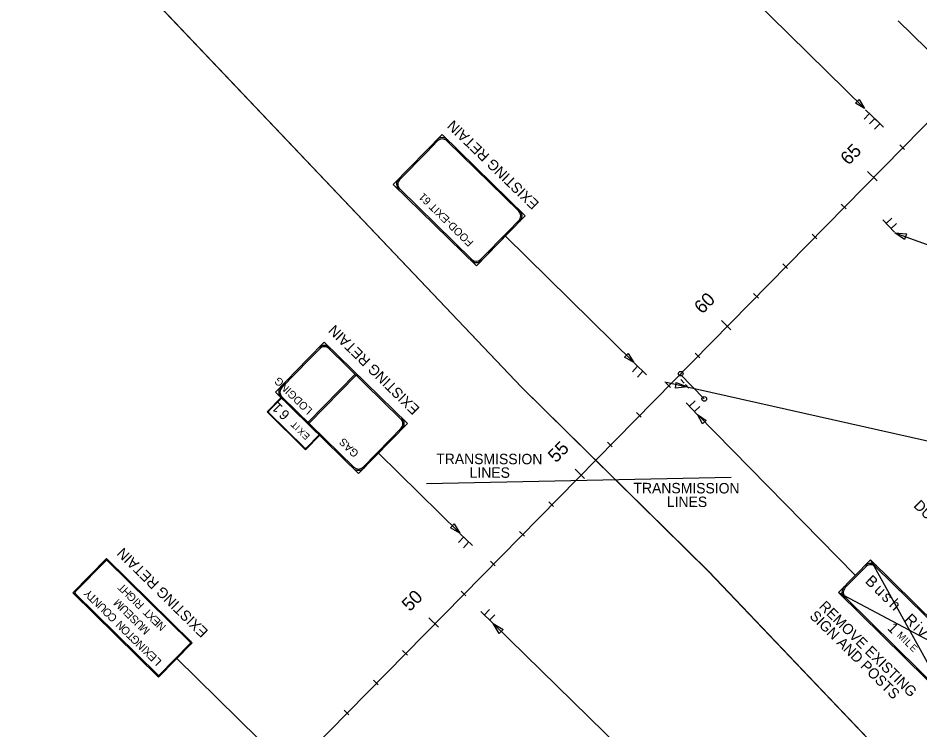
# Model space of a CAD drawing. Extents: x -5665 to 1997148, y 4 to 812485.
# Drawn here: x 1957173 to 1959336, y 794430 to 796136 of the extents above; entities that cross this region are included whole.
import ezdxf

# ---------------------------------------------------------------- set-up
doc = ezdxf.new("R2010")
doc.units = 0
for name, color, linetype in [('RD_HC_CL_Rel', 7, 'Continuous'), ('RD_HC_Data_Tic_Rel', 7, 'Continuous'), ('RD_HC_TX_Rel_Sta50', 7, 'Continuous'), ('RD_PD_Final_TX', 7, 'Continuous'), ('RD_SHT_ShtClip', 7, 'Continuous'), ('RD_SHT_TX', 7, 'Continuous'), ('TR SN EXTRUDED PANEL SIGNS- MOUNTED OVERHEAD', 7, 'Continuous')]:
    doc.layers.add(name, color=color, linetype=linetype)

msp = doc.modelspace()

# ---------------------------------------------------------------- linework, layer by layer
at = {"layer": 'RD_HC_CL_Rel'}
msp.add_line((1957622, 794124.4), (1963740.1, 800343.8), dxfattribs=at)
at = {"layer": 'RD_HC_Data_Tic_Rel'}
for p, q in [((1959299.2, 795820.8), (1959287.8, 795832)), ((1959233.3, 795745.3), (1959210.5, 795767.7)), ((1959158.9, 795678.2), (1959147.5, 795689.4)), ((1959088.8, 795606.9), (1959077.4, 795618.2)), ((1959018.7, 795535.6), (1959007.3, 795546.9)), ((1958948.6, 795464.4), (1958937.2, 795475.6)), ((1958882.7, 795388.9), (1958859.9, 795411.3)), ((1958808.3, 795321.8), (1958796.9, 795333)), ((1958738.2, 795250.5), (1958726.8, 795261.7)), ((1958668, 795179.2), (1958656.6, 795190.4)), ((1958597.9, 795107.9), (1958586.5, 795119.1)), ((1958532.1, 795032.4), (1958509.3, 795054.9)), ((1958457.7, 794965.3), (1958446.3, 794976.6)), ((1958387.5, 794894), (1958376.1, 794905.3)), ((1958317.4, 794822.8), (1958306, 794834)), ((1958247.3, 794751.5), (1958235.9, 794762.7)), ((1958181.4, 794676), (1958158.6, 794698.4)), ((1958107, 794608.9), (1958095.6, 794620.1)), ((1958036.9, 794537.6), (1958025.5, 794548.8)), ((1957966.8, 794466.3), (1957955.4, 794477.5))]:
    msp.add_line(p, q, dxfattribs=at)
at = {"layer": 'RD_PD_Final_TX'}
for points in [[(1959303.9, 795618.3), (1959299.1, 795605.4), (1959275.7, 795621.4)], [(1958750.3, 795248.4), (1958751.9, 795262.1), (1958778.5, 795252)], [(1958336.9, 794670.6), (1958327.3, 794660.8), (1958312.4, 794685)]]:
    msp.add_lwpolyline(points, close=True, dxfattribs=at)
at = {"layer": 'RD_SHT_ShtClip'}
for points in [[(1962404, 800141.4), (1963753.3, 798814), (1964835.2, 797771.3), (1960364.2, 793199.8), (1958829.3, 794809.7), (1958381.6, 795250.1), (1957464.7, 796215.1), (1961650.1, 800469.8)], [(1958379.6, 795252.1), (1958829.6, 794809.5), (1959976.9, 793606), (1955596.7, 789155.3), (1952602.5, 792100.6), (1957064.4, 796636.4)]]:
    msp.add_lwpolyline(points, close=True, dxfattribs=at)
at = {"layer": 'RD_SHT_TX'}
for p, q in [((1959283.6, 796129.4), (1959744.5, 795676)), ((1958152.5, 795020.6), (1958883.8, 795035.8))]:
    msp.add_line(p, q, dxfattribs=at)
at = {"layer": 'TR SN EXTRUDED PANEL SIGNS- MOUNTED OVERHEAD'}
for p, q in [((1959203.3, 795918.8), (1958932.4, 796185.4)), ((1959235.3, 795887.5), (1959205.8, 795916)), ((1959202.3, 795893), (1959214.7, 795905.8)), ((1959215.2, 795881.9), (1959227.6, 795894.7)), ((1959248.6, 795874.5), (1959219, 795903)), ((1959227.4, 795869.2), (1959239.8, 795882)), ((1959268.4, 795656.5), (1959255.5, 795644.2)), ((1959247, 795652.1), (1959275.3, 795622.4)), ((1959280, 795643.3), (1959267.1, 795631)), ((1958649.8, 795310.3), (1958342.1, 795613.2)), ((1959275.7, 795621.4), (1959798.6, 795428.3)), ((1958646.6, 795288.2), (1958659, 795301.1)), ((1958680, 795280.8), (1958650.5, 795309.3)), ((1958658.8, 795275.5), (1958671.2, 795288.4)), ((1958761.3, 795282), (1958818.9, 795223.1)), ((1958762.5, 795269.3), (1958770.8, 795260.8)), ((1958724.1, 795264.2), (1959465.4, 795097.8)), ((1958773.8, 795257.4), (1958782.1, 795248.9)), ((1958775.5, 795213.9), (1958803.8, 795184.2)), ((1958796.9, 795218.3), (1958783.9, 795206)), ((1958808.5, 795205.1), (1958795.6, 795192.8)), ((1959180.6, 794800.3), (1958802.5, 795185.6)), ((1958232.4, 794901.5), (1958037.8, 795093)), ((1958262.8, 794872.1), (1958232.9, 794900.2)), ((1958229.3, 794879.1), (1958241.6, 794892)), ((1958241.7, 794866.5), (1958253.9, 794879.5)), ((1959217.9, 794837.3), (1959404.5, 794499.4)), ((1959140.7, 794758.9), (1959481.6, 794577.8)), ((1958283.2, 794713.3), (1958312.7, 794684.8)), ((1958304.3, 794718.6), (1958291.9, 794705.8)), ((1958316.5, 794705.9), (1958304.1, 794693.1)), ((1958312.4, 794685), (1958618.7, 794385.5)), ((1957750.5, 794407.9), (1957553.7, 794601.5))]:
    msp.add_line(p, q, dxfattribs=at)
for points in [[(1959181.3, 795931.8), (1959190, 795940.6), (1959203.3, 795918.8)], [(1958627.8, 795323.3), (1958636.4, 795332.2), (1958649.8, 795310.3)], [(1958823.8, 795171.5), (1958814.6, 795163.1), (1958802.5, 795185.6)], [(1958210.4, 794914.4), (1958219.1, 794923.3), (1958232.4, 794901.5)]]:
    msp.add_lwpolyline(points, close=True, dxfattribs=at)
for points in [[(1958389.6, 795661.8), (1958190.3, 795856.8), (1958151.3, 795816.9)], [(1958179.5, 795841.3), (1958153.5, 795814.7)], [(1958374.2, 795672.6), (1958201.4, 795841.6)], [(1958151.3, 795816.9), (1958073.3, 795737.2), (1958272.7, 795542.2), (1958350.6, 795622), (1958350.6, 795622)], [(1958153.5, 795814.7), (1958088.5, 795748.3)], [(1958088.8, 795726.4), (1958261.5, 795557.4)], [(1958350.6, 795622), (1958389.6, 795661.8), (1958389.6, 795661.8)], [(1958348.4, 795624.1), (1958374.4, 795650.7)], [(1958283.4, 795557.7), (1958348.4, 795624.1)], [(1958350.6, 795622), (1958285.7, 795555.5)], [(1958107.1, 795163.8), (1957907.7, 795358.8), (1957868.7, 795318.9)], [(1957896.9, 795343.3), (1957871, 795316.7)], [(1958091.6, 795174.6), (1957918.9, 795343.6)], [(1957868.7, 795318.9), (1957790.8, 795239.2), (1957990.1, 795044.2), (1958068.1, 795124), (1958068.1, 795124)], [(1957871, 795316.7), (1957806, 795250.3)], [(1957981.5, 795282.3), (1957869.2, 795167.4)], [(1957984, 795279.8), (1957871.7, 795165)], [(1957804.1, 795226.2), (1957770.5, 795191.9), (1957863, 795101.4), (1957896.6, 795135.7), (1957896.6, 795135.7)], [(1957805.2, 795225.1), (1957775, 795194.2)], [(1957806.2, 795228.4), (1957979, 795059.4)], [(1957775.1, 795189.7), (1957860.7, 795105.9)], [(1958068.1, 795124), (1958107.1, 795163.8), (1958107.1, 795163.8)], [(1958065.9, 795126.1), (1958091.8, 795152.7)], [(1957865.3, 795105.9), (1957895.4, 795136.8)], [(1958000.9, 795059.7), (1958065.9, 795126.1)], [(1957591.2, 794638.7), (1957385.9, 794840.6), (1957305.1, 794758.5), (1957510.4, 794556.5), (1957591.2, 794638.7), (1957591.2, 794638.7), (1957591.2, 794638.7)], [(1957383.8, 794835.1), (1957310.6, 794760.7)], [(1957383.8, 794835.1), (1957383.8, 794835.1), (1957383.8, 794835.1)], [(1957585.7, 794640.7), (1957388.1, 794835.1)], [(1959140.7, 794758.9), (1959404.5, 794499.4), (1959481.6, 794577.8), (1959217.9, 794837.3), (1959140.7, 794758.9), (1959140.7, 794758.9), (1959140.7, 794758.9)], [(1959206.2, 794820.7), (1959157.1, 794770.8)], [(1959206.2, 794820.7), (1959206.2, 794820.7), (1959206.2, 794820.7)], [(1959465, 794589.4), (1959229.8, 794820.9)], [(1957310.7, 794756.4), (1957508.3, 794562)], [(1957310.7, 794756.4), (1957310.7, 794756.4), (1957310.7, 794756.4)], [(1959157.3, 794747.2), (1959392.6, 794515.8)], [(1959157.3, 794747.2), (1959157.3, 794747.2), (1959157.3, 794747.2)], [(1957585.7, 794640.7), (1957585.7, 794640.7), (1957585.7, 794640.7)], [(1957512.5, 794562.1), (1957585.7, 794636.5)], [(1957512.5, 794562.1), (1957512.5, 794562.1), (1957512.5, 794562.1)]]:
    msp.add_lwpolyline(points, dxfattribs=at)
for centre in [(1958762.6, 795283.5), (1958818.9, 795223.1)]:
    msp.add_circle(centre, 5.54, dxfattribs=at)
for centre, radius, start, end in [((1958190.6, 795830.5), 18.6, 45.6377, 135.6379), ((1958190.6, 795830.5), 15.5, 45.6377, 135.6379), ((1958099.6, 795737.5), 18.6, 135.6376, 225.6379), ((1958099.6, 795737.5), 15.5, 135.6376, 225.6379), ((1958363.3, 795661.5), 15.5, 315.6375, 45.6377), ((1958363.3, 795661.5), 18.6, 315.6375, 45.6377), ((1958272.4, 795568.5), 18.6, 225.6379, 315.6375), ((1958272.4, 795568.5), 15.5, 225.6379, 315.6375), ((1957908, 795332.5), 18.6, 45.6377, 135.6379), ((1957908, 795332.5), 15.5, 45.6377, 135.6379), ((1957817, 795239.5), 18.6, 135.6376, 225.6379), ((1957817, 795239.5), 15.5, 135.6376, 225.6379), ((1957777.3, 795192), 4.8, 135.6376, 225.6379), ((1957777.3, 795192), 3.2, 135.6376, 225.6379), ((1958080.8, 795163.5), 15.5, 315.6375, 45.6377), ((1958080.8, 795163.5), 18.6, 315.6375, 45.6377), ((1957863, 795108.2), 4.8, 225.6379, 315.6375), ((1957863, 795108.2), 3.2, 225.6379, 315.6375), ((1957989.8, 795070.5), 18.6, 225.6379, 315.6375), ((1957989.8, 795070.5), 15.5, 225.6379, 315.6375), ((1957386, 794833), 5.4, 45.4705, 135.4707), ((1957386, 794833), 3, 45.4705, 135.4707), ((1959218.1, 794809), 20, 45.4707, 135.4703), ((1959218.1, 794809), 16.7, 45.4707, 135.4703), ((1959169, 794759.1), 20, 135.4703, 225.4705), ((1959169, 794759.1), 16.7, 135.4703, 225.4705), ((1957312.8, 794758.6), 5.4, 135.4705, 225.4707), ((1957312.8, 794758.6), 3, 135.4705, 225.4707), ((1957583.6, 794638.6), 3, 315.4703, 45.4705), ((1957583.6, 794638.6), 5.4, 315.4703, 45.4705), ((1957510.4, 794564.2), 5.4, 225.4707, 315.4703), ((1957510.4, 794564.2), 3, 225.4707, 315.4703)]:
    msp.add_arc(centre, radius, start, end, dxfattribs=at)

# ---------------------------------------------------------------- texts
at = {"layer": 'RD_HC_TX_Rel_Sta50'}
for s, p in [('65', (1959164.8, 795781.3)), ('60', (1958814.1, 795424.8)), ('55', (1958463.5, 795068.4)), ('50', (1958112.8, 794711.9))]:
    msp.add_text(s, height=32, rotation=45.4705, dxfattribs=at).set_placement(p)
at = {"layer": 'RD_SHT_TX'}
for s, p in [('TRANSMISSION', (1958176.2, 795066.9)), ('LINES', (1958256.3, 795034.2)), ('TRANSMISSION', (1958649.1, 794997)), ('LINES', (1958729.2, 794964.2))]:
    msp.add_text(s, height=25, rotation=359.866, dxfattribs=at).set_placement(p)
at = {"layer": 'TR SN EXTRUDED PANEL SIGNS- MOUNTED OVERHEAD'}
for s, height, rotation, p in [('EXISTING RETAIN', 25, 135.9277, (1958424.5, 795692.6)), ('FOOD-EXIT 61', 18.587, 135.6376, (1958267, 795599.5)), ('EXISTING RETAIN', 25, 135.4569, (1958138.1, 795200.6)), ('LODGING', 18.59, 135.6376, (1957880.8, 795197)), ('1', 24, 135.6376, (1957809.6, 795203.9)), ('6', 24, 135.6376, (1957826.8, 795187.1)), ('T', 16, 135.6376, (1957846.8, 795162)), ('I', 16, 135.6376, (1957851.5, 795157.5)), ('X', 16, 135.6376, (1957863.7, 795145.4)), ('E', 16, 135.6376, (1957874.6, 795134.8)), ('GAS', 18.59, 135.6376, (1957992, 795094.2)), ('DURING PHASE 3E CONSTRUCTION.', 25, 315.3323, (1959319.3, 794965.6)), ('EXISTING RETAIN', 25, 135.4569, (1957631, 794666.7)), ('B', 26.7, 315.4705, (1959202.8, 794784.4)), ('T', 19.2, 135.4705, (1957435.3, 794771.9)), ('H', 19.2, 135.4705, (1957447, 794760.3)), ('u', 26.7, 315.4705, (1959224.7, 794762.8)), ('Y', 19.2, 135.4705, (1957355, 794756.6)), ('T', 19.2, 135.4705, (1957364.2, 794747.5)), ('G', 19.2, 135.4705, (1957459.4, 794748.1)), ('s', 26.7, 315.4705, (1959242.4, 794745.4)), ('N', 19.2, 135.4705, (1957376, 794736)), ('U', 19.2, 135.4705, (1957388.4, 794723.8)), ('M', 19.2, 135.4705, (1957429.2, 794730.7)), ('U', 19.2, 135.4705, (1957441.6, 794718.5)), ('I', 19.2, 135.4705, (1957464.8, 794742.9)), ('R', 19.2, 135.4705, (1957477.2, 794730.7)), ('REMOVE EXISTING', 25, 315.4705, (1959092.5, 794724)), ('h', 26.7, 315.4705, (1959260.5, 794727.7)), ('O', 19.2, 135.4705, (1957401.2, 794711.1)), ('C', 19.2, 135.4705, (1957413, 794699.6)), ('E', 19.2, 135.4705, (1957452.6, 794707.8)), ('S', 19.2, 135.4705, (1957465, 794695.5)), ('T', 19.2, 135.4705, (1957495.8, 794712.3)), ('X', 19.2, 135.4705, (1957506.7, 794701.6)), ('SIGN AND POSTS', 25, 315.4705, (1959069.7, 794700.8)), ('R', 26.7, 315.4705, (1959296.6, 794692.1)), ('N', 19.2, 135.4705, (1957432.4, 794680.4)), ('U', 19.2, 135.4705, (1957477.4, 794683.3)), ('M', 19.2, 135.4705, (1957491.2, 794669.8)), ('E', 19.2, 135.4705, (1957517.6, 794690.9)), ('N', 19.2, 135.4705, (1957530, 794678.7)), ('1', 25, 315.4705, (1959256.5, 794671.9)), ('i', 26.7, 315.4705, (1959318.1, 794671)), ('O', 19.2, 135.4705, (1957445.2, 794667.8)), ('T', 19.2, 135.4705, (1957456.2, 794657.1)), ('M', 16.7, 315.4705, (1959279.6, 794655.1)), ('v', 26.7, 315.4705, (1959327.1, 794662.2)), ('G', 19.2, 135.4705, (1957467.9, 794645.5)), ('N', 19.2, 135.4705, (1957480.3, 794633.3)), ('I', 16.7, 315.4705, (1959293.6, 794641.3)), ('L', 16.7, 315.4705, (1959298.7, 794636.3)), ('I', 19.2, 135.4705, (1957485.7, 794628)), ('X', 19.2, 135.4705, (1957497.4, 794616.5)), ('E', 16.7, 315.4705, (1959309.9, 794625.3)), ('E', 19.2, 135.4705, (1957508.3, 794605.7)), ('L', 19.2, 135.4705, (1957519.2, 794595))]:
    msp.add_text(s, height=height, rotation=rotation, dxfattribs=at).set_placement(p)

doc.saveas('drawing.dxf')
